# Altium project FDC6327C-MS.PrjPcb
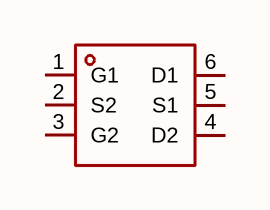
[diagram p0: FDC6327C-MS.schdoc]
1 sheet, 1 parts. Net scope: global (net labels, ports and power ports of the same name join across sheets).

## Sheet FDC6327C-MS.schdoc
size 127 x 101 mm

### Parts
Q?  fdc6327c-ms  [SOT-23-6_L2.9-W1.6-P0.95-LS2.8-BR]  (value not drawn)

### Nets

Not connected (* = marked no-connect by the designer): Q? 1(G1) 2(S2) 3(G2) 4(D2) 5(S1) 6(D1)

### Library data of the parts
Q? = fdc6327c-ms: 数量:1个P沟道;漏源电压(Vdss):20V;连续漏极电流(Id):3A;导通电阻(RDS(on)):100mΩ@4.5V;耗散功率(Pd):1.25W;阈值电压(Vgs(th)):700mV;; Manufacturer: MSKSEMI(美森科); AddInBom: yes; ModelId: 18da8f6c14a34920b3e136b5c401a119; ModelName: SOT-23-6_L2.9-W1.6-H1.5-LS2.8-P0.95; ModelTransform: 110.73671,114.173,0,180,0,0,0.001,-0.003,0; Number: 1个P沟道; Drain to Source Voltage: 20V; Current - Continuous Drain(Id): 3A; Pd - Power Dissipation: 1.25W; Gate Threshold Voltage (Vgs(th)): 700mV; Gate Charge(Qg): 4.8nC@4.5V; Input Capacitance(Ciss): 350pF; Reverse Transfer Capacitance (Crss@Vds): 50pF; Type: P沟道; Output Capacitance(Coss): 65pF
